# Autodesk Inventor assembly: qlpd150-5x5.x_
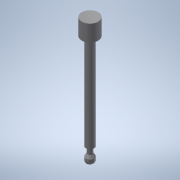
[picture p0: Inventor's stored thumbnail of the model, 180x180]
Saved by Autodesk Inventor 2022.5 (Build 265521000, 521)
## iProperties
Part Number: qlpd150-5x5.x_
Material: 一般
Document SubType Name: Assembly
Designer: ImaoCorp
Sending System: SOLIDWORKS 2017-2017317
MC: AMD64
MC_MODEL: Intel64 Family 6 Model 60 Stepping 3, GenuineIntel
OS: Windows_NT
FRU: Parasolid Version 29.0, build 201,  4-17-2017
FORMAT: text
GUISE: transmit
KEY: qlpd150-5x5
FILE: qlpd150-5x5.x_t
DATE: Wed Sep 04 15:45:16 2019
Author: ImaoCorp
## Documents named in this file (3)
- X:\14_SW2022-Inv2022\00_全2023-1023新製品(TCC)まで\q\qlpd150-5x5\QLPD150-5X5.iam
- X:\14_SW2022-Inv2022\00_全2023-1023新製品(TCC)まで\q\qlpd150-5x5\qlpd150-5x5_01.ipt
- X:\14_SW2022-Inv2022\00_全2023-1023新製品(TCC)まで\q\qlpd150-5x5\qlpd150-5x5_02.ipt
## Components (2 placed, 2 different names)
1. qlpd150-5x5_01
2. qlpd150-5x5_02
